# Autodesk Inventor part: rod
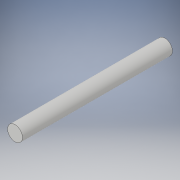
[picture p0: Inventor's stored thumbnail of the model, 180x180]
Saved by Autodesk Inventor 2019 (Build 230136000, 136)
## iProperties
Created: 2021-07
Part Number: rod
Material: Generic
Document SubType Name: Modeling
Designer: Avinash
Density: 1 g/cm^3
Appearance: Default
Author: Avinash
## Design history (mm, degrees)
sketch "Sketch1"
  geometry: C1 r 5 at (0, 0); 1 further point
  constraints: 1 centre point, 1 coincident
  dimensions: "d0" = 10 diameter of C1
extrude "Extrusion1" new body sketch "Sketch1" distance "d1" = 100; taper "d2" = 0 deg
body "Solid1"
